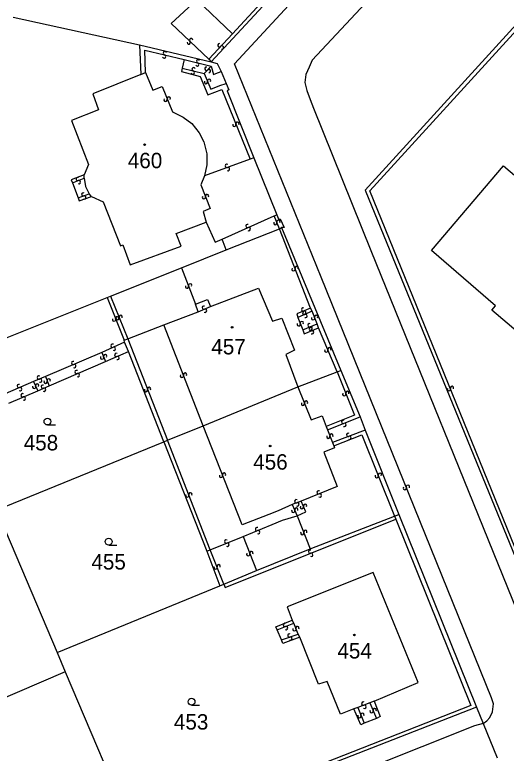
# Model space of a CAD drawing. Extents: x -600391 to -599491, y -1160176 to -1159402.
# Drawn here: x -599892 to -599837.9, y -1160042.2 to -1159960.8 of the extents above; entities that cross this region are included whole.
import ezdxf

# ---------------------------------------------------------------- set-up
doc = ezdxf.new("R2010")
doc.units = 0
for name, color, linetype in [('Level 1', 7, 'Continuous'), ('Level 13', 7, 'Continuous'), ('Level 3', 7, 'Continuous'), ('Level 4', 7, 'Continuous'), ('Level 5', 7, 'Continuous')]:
    doc.layers.add(name, color=color, linetype=linetype)

msp = doc.modelspace()

# ---------------------------------------------------------------- linework, layer by layer
at = {"layer": 'Level 1'}
for points in [[(-599852.3, -1159946.48), (-599870.36, -1159965.98)], [(-599892.18, -1159961.06), (-599878.25, -1159964.12)], [(-599836.35, -1159961.44), (-599853.38, -1159980.13), (-599835.49, -1160023.94)], [(-599878.25, -1159964.12), (-599878.09, -1159967.39)], [(-599878.25, -1159964.12), (-599870.36, -1159965.98)], [(-599870.36, -1159965.98), (-599869.68, -1159966.19), (-599869.25, -1159967.07)], [(-599878.09, -1159967.39), (-599883.4, -1159969.52), (-599882.77, -1159971.27), (-599885.73, -1159972.46), (-599883.85, -1159977.31), (-599884.35, -1159978.45)], [(-599869.25, -1159967.07), (-599868.69, -1159968.38)], [(-599868.69, -1159968.38), (-599868.43, -1159969.07), (-599868.6, -1159969.18), (-599865.66, -1159976.55)], [(-599865.66, -1159976.55), (-599863.14, -1159982.84)], [(-599818.44, -1159994.22), (-599810.51, -1160000.98), (-599818.49, -1160010.25), (-599825.44, -1160004.41), (-599825.9, -1160004.85), (-599839.43, -1159993.35), (-599839.05, -1159992.87), (-599846.11, -1159986.79), (-599838.15, -1159977.46), (-599830.14, -1159984.27)], [(-599884.35, -1159978.45), (-599885.76, -1159978.99), (-599885.62, -1159979.32)], [(-599885.62, -1159979.32), (-599885, -1159980.98)], [(-599885, -1159980.98), (-599884.89, -1159981.29), (-599883.52, -1159980.81)], [(-599883.52, -1159980.81), (-599882.25, -1159981.43), (-599880.35, -1159986.25), (-599880.08, -1159986.15), (-599879.28, -1159988.34), (-599873.67, -1159986.29), (-599874.22, -1159984.92), (-599870.9, -1159983.65)], [(-599863.14, -1159982.84), (-599862.92, -1159983.39), (-599862.75, -1159983.3), (-599862.32, -1159984.23), (-599862.6, -1159984.25)], [(-599870.9, -1159983.65), (-599869.92, -1159985.86), (-599869.16, -1159985.52)], [(-599868.7, -1159986.72), (-599862.82, -1159984.39)], [(-599862.82, -1159984.39), (-599862.6, -1159984.25)], [(-599862.6, -1159984.25), (-599856.07, -1160000.01)], [(-599868.7, -1159986.72), (-599869.16, -1159985.52)], [(-599873.61, -1159988.69), (-599868.7, -1159986.72)], [(-599881.46, -1159991.8), (-599873.61, -1159988.69)], [(-599870.42, -1159992.96), (-599865.15, -1159990.92), (-599863.59, -1159994.57), (-599862.57, -1159994.22), (-599861.18, -1159997.75), (-599862.15, -1159998.22), (-599860.81, -1160001.78)], [(-599900.74, -1159999.53), (-599881.81, -1159991.97)], [(-599881.81, -1159991.97), (-599881.46, -1159991.8)], [(-599872.08, -1159992.69), (-599870.78, -1159992.18), (-599870.42, -1159992.96)], [(-599871.79, -1159993.55), (-599872.08, -1159992.69)], [(-599875.57, -1159994.97), (-599871.79, -1159993.55)], [(-599879.54, -1159996.51), (-599875.57, -1159994.97)], [(-599879.95, -1159996.67), (-599879.54, -1159996.51)], [(-599879.89, -1159996.86), (-599879.95, -1159996.67)], [(-599879.48, -1159997.9), (-599879.89, -1159996.86)], [(-599875.57, -1160007.85), (-599879.48, -1159997.9)], [(-599860.81, -1160001.78), (-599856.49, -1160000.16)], [(-599856.49, -1160000.16), (-599856.07, -1160000.01)], [(-599856.07, -1160000.01), (-599853.94, -1160005.11)], [(-599871.25, -1160006.08), (-599860.81, -1160001.78)], [(-599853.94, -1160005.11), (-599853.39, -1160006.56)], [(-599875.18, -1160007.67), (-599871.25, -1160006.08)], [(-599853.39, -1160006.56), (-599849.7, -1160015.86)], [(-599893.98, -1160015.34), (-599875.57, -1160007.85)], [(-599875.57, -1160007.85), (-599875.18, -1160007.67)], [(-599875.57, -1160007.85), (-599870.85, -1160019.9)], [(-599859.45, -1160019.66), (-599850.15, -1160016.04)], [(-599850.15, -1160016.04), (-599849.7, -1160015.86)], [(-599849.7, -1160015.86), (-599841.12, -1160037.1)], [(-599893.02, -1160017.68), (-599887.32, -1160031.07)], [(-599865.38, -1160022.05), (-599859.45, -1160019.66)], [(-599870.85, -1160019.9), (-599869.39, -1160023.71)], [(-599868.95, -1160023.53), (-599865.38, -1160022.05)], [(-599852.41, -1160036.42), (-599847.55, -1160034.39), (-599852.53, -1160022.25), (-599862, -1160026.02), (-599861.42, -1160027.49)], [(-599887.32, -1160031.07), (-599869.39, -1160023.71)], [(-599869.39, -1160023.71), (-599868.95, -1160023.53)], [(-599863.08, -1160028.56), (-599863.25, -1160028.23), (-599861.42, -1160027.49)], [(-599862.6, -1160029.68), (-599863.08, -1160028.56)], [(-599860.61, -1160029.37), (-599862.45, -1160030.08), (-599862.6, -1160029.68)], [(-599854.64, -1160037.29), (-599856.12, -1160037.87), (-599857.6, -1160034.25), (-599858.54, -1160034.56), (-599860.61, -1160029.37)], [(-599887.32, -1160031.07), (-599886.45, -1160033.19)], [(-599886.45, -1160033.19), (-599905.23, -1160041.29)], [(-599886.45, -1160033.19), (-599878.71, -1160051.41)], [(-599852.41, -1160036.42), (-599851.73, -1160038.13), (-599852.16, -1160038.33)], [(-599841.12, -1160037.1), (-599878.65, -1160051.73)], [(-599853.49, -1160038.86), (-599853.89, -1160039.02), (-599854.64, -1160037.29)], [(-599841.12, -1160037.1), (-599840.4, -1160038.88)], [(-599852.16, -1160038.33), (-599853.49, -1160038.86)], [(-599840.4, -1160038.88), (-599838.86, -1160042.68)]]:
    msp.add_lwpolyline(points, dxfattribs=at)
at = {"layer": 'Level 13'}
for centre, start, end in [((-599872.563, -1159963.587), 353.72179, 226.31179), ((-599872.818, -1159963.853), 173.93625, 46.03425), ((-599869.454, -1159964.164), 84.07452, 316.66452), ((-599869.186, -1159964.417), 264.28898, 136.38698), ((-599875.542, -1159965.399), 204.24046, 76.83046), ((-599875.457, -1159965.041), 24.45492, 256.55292), ((-599871.885, -1159966.268), 203.16744, 75.75744), ((-599871.794, -1159965.911), 23.38189, 255.47989), ((-599872.293, -1159966.802), 23.16879, 255.26679), ((-599870.873, -1159966.743), 83.59038, 316.18038), ((-599870.608, -1159966.998), 263.80483, 135.90283), ((-599872.386, -1159967.158), 202.95434, 75.54434), ((-599870.929, -1159968.212), 150.55876, 23.14876), ((-599870.59, -1159968.068), 330.77321, 202.87121), ((-599875.371, -1159970.169), 149.48693, 22.07693), ((-599875.029, -1159970.032), 329.70139, 201.79939), ((-599867.801, -1159972.939), 149.31987, 21.90987), ((-599867.459, -1159972.802), 329.53433, 201.63233), ((-599868.633, -1159977.457), 57.5261, 290.1161), ((-599868.507, -1159977.803), 237.74055, 109.83855), ((-599885.056, -1159978.898), 59.01717, 291.11517), ((-599884.923, -1159979.241), 238.80271, 111.39271), ((-599884.45, -1159980.595), 56.7882, 288.88619), ((-599870.808, -1159980.774), 328.75978, 200.85778), ((-599884.33, -1159980.944), 236.57374, 109.16374), ((-599871.152, -1159980.906), 148.54533, 21.13533), ((-599866.373, -1159984.081), 61.36305, 293.46105), ((-599863.29, -1159983.751), 150.62, 22.718), ((-599862.951, -1159983.608), 330.40555, 202.99555), ((-599866.226, -1159984.418), 241.14859, 113.73859), ((-599861.292, -1159988.835), 148.66431, 20.7623), ((-599860.948, -1159988.704), 328.44985, 201.03985), ((-599872.667, -1159990.626), 328.30459, 200.40258), ((-599873.012, -1159990.755), 148.09013, 20.68013), ((-599871.171, -1159993.08), 60.6722, 292.77019), ((-599871.028, -1159993.419), 240.45774, 113.04774), ((-599860.239, -1159993.279), 59.34857, 291.93857), ((-599860.105, -1159993.652), 61.32491, 293.91491), ((-599860.102, -1159993.621), 239.56302, 111.66102), ((-599881.051, -1159994.387), 148.7492, 21.3392), ((-599880.708, -1159994.254), 328.96365, 201.06165), ((-599880.671, -1159994.229), 149.33621, 21.92621), ((-599880.329, -1159994.092), 329.55067, 201.64867), ((-599859.956, -1159993.989), 241.53936, 113.63736), ((-599859.131, -1159994.239), 149.87626, 21.97426), ((-599858.79, -1159994.1), 329.66181, 202.25181), ((-599860.711, -1159994.909), 149.47387, 22.06387), ((-599860.369, -1159994.772), 329.68832, 201.78632), ((-599859.537, -1159995.018), 59.29829, 291.39629), ((-599859.388, -1159995.449), 59.60773, 291.70572), ((-599859.402, -1159995.361), 239.08384, 111.67384), ((-599859.251, -1159995.791), 239.39327, 111.98327), ((-599881.217, -1159997.273), 62.04958, 294.63958), ((-599881.064, -1159997.608), 242.26403, 114.36203), ((-599857.681, -1159997.8), 150.10111, 22.19911), ((-599857.34, -1159997.66), 329.88666, 202.47666), ((-599882.372, -1159998.566), 148.55117, 21.14117), ((-599882.028, -1159998.434), 328.76562, 200.86362), ((-599880.811, -1159998.27), 60.68056, 292.77856), ((-599880.668, -1159998.609), 240.46611, 113.05611), ((-599885.571, -1159999.17), 60.12337, 292.71337), ((-599885.43, -1159999.51), 240.33783, 112.43583), ((-599885.182, -1160000.16), 60.74954, 292.84753), ((-599889.333, -1160000.771), 60.62435, 293.21435), ((-599889.188, -1160001.11), 240.83881, 112.93681), ((-599888.248, -1160001.092), 329.46696, 201.56496), ((-599885.038, -1160000.499), 240.53508, 113.12508), ((-599873.583, -1160000.585), 148.62075, 20.71875), ((-599873.238, -1160000.454), 328.40629, 200.99629), ((-599891.541, -1160001.71), 60.24596, 292.83596), ((-599891.399, -1160002.05), 240.46041, 112.55841), ((-599889.858, -1160001.804), 151.17338, 23.76338), ((-599889.521, -1160001.656), 331.38784, 203.48583), ((-599888.914, -1160001.781), 61.50511, 293.60311), ((-599888.591, -1160001.228), 149.25251, 21.84251), ((-599877.188, -1160002.024), 328.71238, 200.81038), ((-599843.839, -1160001.921), 329.27619, 201.86619), ((-599891.121, -1160002.73), 60.37533, 292.47333), ((-599888.765, -1160002.118), 241.29066, 113.88066), ((-599877.532, -1160002.156), 148.49792, 21.08792), ((-599855.711, -1160002.607), 148.8768, 21.4668), ((-599855.368, -1160002.473), 329.09126, 201.18925), ((-599844.182, -1160002.058), 149.49064, 21.58864), ((-599890.979, -1160003.07), 240.16088, 112.75088), ((-599859.898, -1160003.533), 329.36386, 201.46186), ((-599860.241, -1160003.668), 149.14941, 21.73941), ((-599855.815, -1160005.648), 58.65378, 290.75178), ((-599855.684, -1160005.992), 238.43933, 111.02933), ((-599857.452, -1160007.297), 148.68088, 21.27088), ((-599857.108, -1160007.164), 328.89533, 200.99333), ((-599855.265, -1160007.078), 58.07871, 290.66871), ((-599855.136, -1160007.423), 238.29316, 110.39116), ((-599869.272, -1160011.606), 148.89342, 20.99141), ((-599868.928, -1160011.473), 328.67896, 201.26896), ((-599852.121, -1160011.628), 149.04783, 21.63783), ((-599851.778, -1160011.493), 329.26229, 201.36029), ((-599858.529, -1160013.419), 59.4073, 291.9973), ((-599849.032, -1160012.948), 149.41882, 21.51682), ((-599848.689, -1160012.812), 329.20437, 201.79437), ((-599872.992, -1160013.776), 148.71474, 20.81273), ((-599872.648, -1160013.644), 328.50028, 201.09028), ((-599858.392, -1160013.761), 239.62176, 111.71976), ((-599860.994, -1160014.408), 57.84236, 290.43236), ((-599860.866, -1160014.753), 238.05681, 110.15481), ((-599860.021, -1160014.908), 330.47599, 203.06599), ((-599861.319, -1160015.472), 150.52262, 23.11262), ((-599860.98, -1160015.328), 330.73708, 202.83508), ((-599860.36, -1160015.051), 150.69044, 22.78844), ((-599865.308, -1160017.469), 59.69864, 291.79664), ((-599865.171, -1160017.811), 239.48419, 112.07419), ((-599860.332, -1160017.907), 148.60601, 21.19601), ((-599859.988, -1160017.774), 328.82047, 200.91847), ((-599868.707, -1160018.848), 59.28291, 291.38091), ((-599868.572, -1160019.191), 239.06846, 111.65846), ((-599859.467, -1160019.968), 59.13207, 291.23007), ((-599866.272, -1160020.235), 148.24683, 20.83683), ((-599865.927, -1160020.105), 328.46128, 200.55928), ((-599859.333, -1160020.311), 238.91762, 111.50762), ((-599869.539, -1160021.572), 328.93355, 201.52355), ((-599869.882, -1160021.707), 149.14801, 21.246), ((-599862.235, -1160028.028), 58.68398, 290.78198), ((-599862.104, -1160028.372), 238.46953, 111.05953), ((-599861.191, -1160028.509), 149.75287, 21.85087), ((-599860.849, -1160028.371), 329.53841, 202.12841), ((-599861.749, -1160029.185), 56.64883, 288.74683), ((-599861.63, -1160029.534), 236.43438, 109.02438), ((-599853.608, -1160036.699), 58.95969, 291.54969), ((-599853.473, -1160037.042), 239.17414, 111.27214), ((-599852.691, -1160037.539), 149.47175, 22.06175), ((-599852.349, -1160037.402), 329.68621, 201.7842), ((-599854.03, -1160038.071), 150.15555, 22.74555), ((-599853.69, -1160037.93), 330.37001, 202.468)]:
    msp.add_arc(centre, 0.184, start, end, dxfattribs=at)
at = {"layer": 'Level 3'}
for points in [[(-599865.14, -1159933.87), (-599852.89, -1159946.47), (-599868.02, -1159962.9)], [(-599840.4, -1160038.88), (-599839.99, -1160038.6), (-599839.65, -1160038.21), (-599839.36, -1160037.6), (-599839.27, -1160036.72), (-599839.47, -1160036.06), (-599858.24, -1159989.71), (-599867.79, -1159966.21), (-599851.76, -1159948.82), (-599850.87, -1159947.82)], [(-599846.4, -1159952.01), (-599848.08, -1159953.82), (-599859.23, -1159965.79), (-599859.58, -1159966.58), (-599859.93, -1159967.38), (-599860.05, -1159968.25), (-599859.84, -1159969.13), (-599859.47, -1159970.12), (-599859.1, -1159971.11), (-599852.79, -1159986.79), (-599837.18, -1160025.28), (-599821.6, -1160063.84), (-599805.47, -1160103.79), (-599793.95, -1160133.25), (-599793.45, -1160134.12), (-599792.68, -1160134.75), (-599791.97, -1160134.96), (-599791.42, -1160135), (-599790.84, -1160134.89)], [(-599870.62, -1159965.68), (-599874.76, -1159961.76), (-599871.95, -1159959.12), (-599868.02, -1159962.9)], [(-599835.15, -1160023.79), (-599852.87, -1159980.19), (-599836.32, -1159962.05), (-599816.82, -1159978.63), (-599818.91, -1159980.97), (-599818.55, -1159981.29)], [(-599868.02, -1159962.9), (-599870.62, -1159965.68)], [(-599877.6, -1159967.17), (-599877.68, -1159964.72), (-599873.32, -1159965.72)], [(-599873.32, -1159965.72), (-599873.54, -1159966.67)], [(-599873.32, -1159965.72), (-599870.35, -1159966.46)], [(-599870.62, -1159965.68), (-599870.36, -1159965.98)], [(-599873.54, -1159966.67), (-599873.64, -1159967.04), (-599871.58, -1159967.59), (-599870.71, -1159969.62), (-599869.19, -1159969.04), (-599866.07, -1159976.7)], [(-599873.54, -1159966.67), (-599871.13, -1159967.28)], [(-599870.35, -1159966.46), (-599871.13, -1159967.28)], [(-599870.35, -1159966.46), (-599870.09, -1159967.39), (-599869.83, -1159967.29), (-599869.25, -1159967.07)], [(-599878.09, -1159967.39), (-599877.6, -1159967.17)], [(-599877.6, -1159967.17), (-599876.78, -1159969.1), (-599875.77, -1159968.7), (-599874.62, -1159971.5), (-599873.43, -1159972.09), (-599872.49, -1159972.79), (-599871.68, -1159973.81), (-599871.16, -1159974.81), (-599870.83, -1159976.12), (-599870.82, -1159977.34), (-599871.08, -1159978.56)], [(-599871.13, -1159967.28), (-599870.39, -1159968.99), (-599869.39, -1159968.61), (-599868.69, -1159968.38)], [(-599865.66, -1159976.55), (-599866.07, -1159976.7)], [(-599866.07, -1159976.7), (-599871.08, -1159978.56)], [(-599885.62, -1159979.32), (-599884.36, -1159978.82)], [(-599884.36, -1159978.82), (-599884.35, -1159978.45)], [(-599884.36, -1159978.82), (-599884.19, -1159979.72), (-599883.78, -1159980.55)], [(-599871.08, -1159978.56), (-599871.5, -1159979.53), (-599870.47, -1159982.16), (-599871.24, -1159982.46), (-599870.9, -1159983.65)], [(-599885, -1159980.98), (-599883.78, -1159980.55)], [(-599883.52, -1159980.81), (-599883.78, -1159980.55)], [(-599869.16, -1159985.52), (-599863.43, -1159982.97)], [(-599863.43, -1159982.97), (-599863.14, -1159982.84)], [(-599862.82, -1159984.39), (-599863.43, -1159982.97)], [(-599859.41, -1159993.14), (-599862.82, -1159984.39)], [(-599873.61, -1159988.69), (-599872.08, -1159992.69)], [(-599881.81, -1159991.97), (-599879.95, -1159996.67)], [(-599881.46, -1159991.8), (-599879.54, -1159996.51)], [(-599871.79, -1159993.55), (-599870.42, -1159992.96)], [(-599859.41, -1159993.14), (-599860.93, -1159993.76), (-599860.81, -1159994.17)], [(-599859.25, -1159993.47), (-599860.81, -1159994.17)], [(-599859.25, -1159993.47), (-599859.41, -1159993.14)], [(-599858.67, -1159994.87), (-599859.25, -1159993.47)], [(-599860.81, -1159994.17), (-599860.26, -1159995.51)], [(-599871.25, -1160006.08), (-599875.57, -1159994.97)], [(-599860.26, -1159995.51), (-599858.67, -1159994.87)], [(-599860.26, -1159995.51), (-599860.12, -1159995.94), (-599858.53, -1159995.29)], [(-599858.53, -1159995.29), (-599858.67, -1159994.87)], [(-599856.49, -1160000.16), (-599858.53, -1159995.29)], [(-599879.89, -1159996.86), (-599882.39, -1159998.02)], [(-599879.54, -1159996.51), (-599875.18, -1160007.67)], [(-599882.39, -1159998.02), (-599888.62, -1160000.66)], [(-599882.39, -1159998.02), (-599882.01, -1159998.99)], [(-599882.01, -1159998.99), (-599879.48, -1159997.9)], [(-599888.21, -1160001.67), (-599882.01, -1159998.99)], [(-599856.49, -1160000.16), (-599854.59, -1160004.93), (-599857.7, -1160006.16)], [(-599888.62, -1160000.66), (-599889.91, -1160001.22)], [(-599888.62, -1160000.66), (-599888.21, -1160001.67)], [(-599889.91, -1160001.22), (-599893.03, -1160002.55)], [(-599889.91, -1160001.22), (-599889.46, -1160002.23)], [(-599889.46, -1160002.23), (-599888.21, -1160001.67)], [(-599860.81, -1160001.78), (-599859.34, -1160005.42), (-599858.14, -1160004.98), (-599857.7, -1160006.16)], [(-599892.64, -1160003.58), (-599889.46, -1160002.23)], [(-599857.56, -1160006.52), (-599853.94, -1160005.11)], [(-599861.42, -1160014.77), (-599862.98, -1160015.44), (-599863.99, -1160015.86), (-599866.94, -1160017.01), (-599871.25, -1160006.08)], [(-599857.7, -1160006.16), (-599857.56, -1160006.52)], [(-599857.56, -1160006.52), (-599857, -1160007.94)], [(-599853.39, -1160006.56), (-599857, -1160007.94)], [(-599856.84, -1160008.28), (-599853.75, -1160007.08), (-599850.15, -1160016.04)], [(-599870.46, -1160019.75), (-599875.18, -1160007.67)], [(-599856.84, -1160008.28), (-599856.76, -1160008.52), (-599857.94, -1160008.98), (-599856.48, -1160012.78), (-599860.44, -1160014.4)], [(-599857, -1160007.94), (-599856.84, -1160008.28)], [(-599860.44, -1160014.4), (-599861.42, -1160014.77)], [(-599861.42, -1160014.77), (-599860.88, -1160016.02)], [(-599860.88, -1160016.02), (-599859.94, -1160015.56), (-599860.44, -1160014.4)], [(-599850.01, -1160016.39), (-599841.76, -1160036.9), (-599878.71, -1160051.41)], [(-599868.95, -1160023.53), (-599868.8, -1160023.89), (-599850.01, -1160016.39)], [(-599866.83, -1160018.29), (-599863.64, -1160016.98), (-599862.52, -1160016.48), (-599860.88, -1160016.02)], [(-599860.88, -1160016.02), (-599859.45, -1160019.66)], [(-599850.15, -1160016.04), (-599850.01, -1160016.39)], [(-599870.46, -1160019.75), (-599866.83, -1160018.29)], [(-599866.83, -1160018.29), (-599865.38, -1160022.05)], [(-599870.85, -1160019.9), (-599870.46, -1160019.75)], [(-599868.95, -1160023.53), (-599870.46, -1160019.75)], [(-599863.08, -1160028.56), (-599861.26, -1160027.85)], [(-599861.26, -1160027.85), (-599861.42, -1160027.49)], [(-599860.77, -1160029.04), (-599861.26, -1160027.85)], [(-599862.6, -1160029.68), (-599860.77, -1160029.04)], [(-599860.61, -1160029.37), (-599860.77, -1160029.04)], [(-599852.87, -1160036.6), (-599854.22, -1160037.14)], [(-599852.41, -1160036.42), (-599852.87, -1160036.6)], [(-599852.87, -1160036.6), (-599852.16, -1160038.33)], [(-599854.22, -1160037.14), (-599854.64, -1160037.29)], [(-599854.22, -1160037.14), (-599853.49, -1160038.86)], [(-599840.4, -1160038.88), (-599841.34, -1160039.13), (-599864.36, -1160048.33), (-599874.5, -1160052.17), (-599880.99, -1160054.5), (-599902.43, -1160061.94), (-599908.17, -1160063.85), (-599916.7, -1160066.63)]]:
    msp.add_lwpolyline(points, dxfattribs=at)
at = {"layer": 'Level 5'}
for p, q in [((-599888.39, -1160006), (-599887.515, -1160006)), ((-599881.64, -1160019.23), (-599880.765, -1160019.23)), ((-599872.52, -1160036.86), (-599871.645, -1160036.86))]:
    msp.add_line(p, q, dxfattribs=at)
for centre, radius in [((-599877.69, -1159975.11), 0.09), ((-599877.69, -1159975.11), 0.0521), ((-599868.05, -1159995.24), 0.09), ((-599868.05, -1159995.24), 0.0521), ((-599888.39, -1160005.625), 0.375), ((-599863.86, -1160008.32), 0.09), ((-599863.86, -1160008.32), 0.0521), ((-599881.64, -1160018.855), 0.375), ((-599854.59, -1160029.13), 0.09), ((-599854.59, -1160029.13), 0.0521), ((-599872.52, -1160036.485), 0.375)]:
    msp.add_circle(centre, radius, dxfattribs=at)

# ---------------------------------------------------------------- texts
at = {"layer": 'Level 4'}
for s, p in [('460', (-599879.538, -1159977.71)), ('457', (-599870.34, -1159998.22)), ('458', (-599891.003, -1160008.8)), ('456', (-599865.726, -1160010.92)), ('455', (-599883.547, -1160021.93)), ('454', (-599856.456, -1160031.73)), ('453', (-599874.462, -1160039.56))]:
    msp.add_text(s, height=1.7, dxfattribs=at).set_placement(p)

doc.saveas('drawing.dxf')
